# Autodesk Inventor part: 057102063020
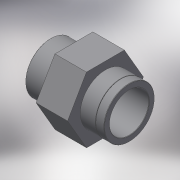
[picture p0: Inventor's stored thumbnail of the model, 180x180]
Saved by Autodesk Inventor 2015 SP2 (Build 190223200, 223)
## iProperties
Created: 2017-10
Part Number: 057102063020
Material: Generic
Description: PLASSON AD. SOCKET REINF.PVC 63-2"
Document SubType Name: Modeling
Designer: KIM
Density: 1 g/cm^3
Appearance: Default
Author: KIM
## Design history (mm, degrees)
derived "057102.ipt"
feature "Solid1::057102.ipt"
tag "TaggingFeature1"
body "Solid1"
other parameters: "d0" = 68, "d1" = 63, "d3" = 56.656, "d4" = 50.4, "d5" = 38, "d6" = 26, "d7" = 75.6, "d8" = 72.45, "d10" = 18.2, "d13" = 0, "d14" = 0.63, "d15" = 16, "d16" = 6.5, "d17" = 75.6, "d18" = 0.1, "d_" = 63, "G_" = 56.656, "B_" = 16, "l_" = 38, "lt_" = 26, "H_" = 68
